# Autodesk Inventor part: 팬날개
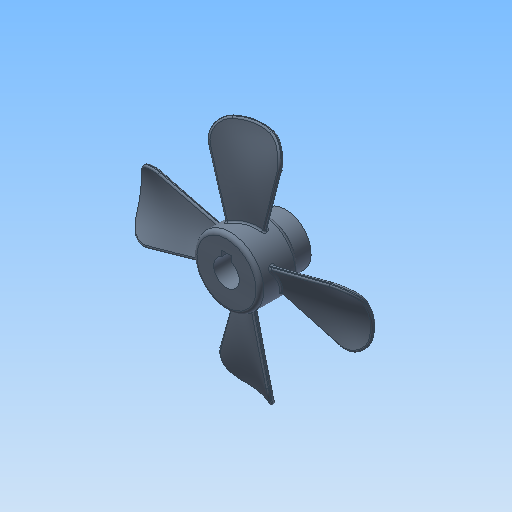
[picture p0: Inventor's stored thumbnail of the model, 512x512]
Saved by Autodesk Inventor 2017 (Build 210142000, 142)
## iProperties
Company: 한국ATC센터
Created: 2016-06
Part Number: 팬날개
Document SubType Name: Modeling
Designer: mdu
Density: 1.493 g/cm^3
Material: ABS 플라스틱
Mass: 1497.56 g
Surface Area: 466.268 cm^2
Volume: 190.529 cm^3
Appearance: 강청색
Author: mdu
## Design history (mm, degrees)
sketch "스케치1"
  geometry: L1 (-15, 0)-(15, 0); L2 (-15, 0)-(-15, 17); L3 (-15, 17)-(5, 17); L4 (5, 17)-(5, 13); L5 (5, 13)-(15, 13); L6 (15, 13)-(15, 0); 2 further points
  constraints: 12 end point, 3 parallel, 2 perpendicular, 1 coincident, 1 horizontal, 1 midpoint
  dimensions: "d0" = 30 distance of L1.start L1.end; "d8" = 34 diameter of L3 L1; "d10" = 26 diameter of L5 L1; "d32" = 20 distance of L2.end L3.end
revolve "회전1" sketch "스케치1" stored, may be unused: angle "d11" = 90 deg
node "작업 평면2"
sketch "스케치7"
  geometry: L1 (-15, 17)-(5, 17) reference; L2 (-15, -17)-(5, -17) reference; L3 (-5, 17)-(-5, -17); A1 r 35 centre (-36.399, -13.457) between (-2, -7) and (-8, 7); 1 further point
  constraints: 2 end point, 2 midpoint, 2 point on circle, 1 centre point
  dimensions: "d36" = 35 radius of A1; "d37" = 10 distance from line of A1.start L2; "d38" = 10 distance from line of A1.end L1; "d45" = 3 distance from line of A1.end L3; "d46" = 3 distance from line of A1.start L3
sketch "3D 스케치1"
  geometry: L1 through (0, 0) direction (1, 0) reference; L2 through (0, 0) direction (1, 0) reference; 13 other entities
  constraints: 2 collinear
  node "투영 원본 위치 스케치7"
sketch "스케치8"
  geometry: L1 (-15, 17)-(5, 17) reference; L2 (-15, -17)-(5, -17) reference; L3 (-5, 17)-(-5, -17); A1 r 30 centre (-28.74, -3.591) between (-3, -19) and (-9, 19); 1 further point
  constraints: 2 end point, 2 midpoint, 2 point on circle, 1 centre point
  dimensions: "d43" = 30 radius of A1; "d47" = 4 distance from line of A1.end L3; "d48" = 2 distance from line of A1.start L3; "d58" = 2 distance from line of A1.end L1; "d59" = 2 distance from line of A1.start L2
sketch "3D 스케치2"
sketch "3D 스케치3"
feature "경계 패치1" sketch "3D 스케치2", "3D 스케치3" dims "d50" = 0
feature "연장1" dims "d55" = 2
feature "두껍게 하기1" dims "d51" = 2, "d52" = 2
sketch "스케치9"
  geometry: C1 r 59 at (0, 0); 1 further point
  constraints: 1 centre point, 1 coincident
  dimensions: "d60" = 118 diameter of C1
extrude "돌출2" sketch "스케치9" distance "d62" = 200; taper "d63" = 0 deg
fillet "모깎기6" dims "d64" = 10
fillet "모깎기7" dims "d66" = 0.8
fillet "모깎기8" dims "d67" = 0.8
sketch "스케치2"
  geometry: L1 (-2.5, 6)-(-2.5, 8.8); L2 (-2.5, 8.8)-(2.5, 8.8); L3 (2.5, 8.8)-(2.5, 6); A1 r 6.5 centre (0, 0) between (-2.5, 6) and (2.5, 6); 1 further point
  constraints: 6 end point, 2 parallel, 2 point on circle, 1 centre point, 1 coincident, 1 horizontal, 1 vertical
  dimensions: "d12" = 13 diameter of A1; "d13" = 5 distance of L1.end L2.end; "d14" = 15.3 dimension on A1 L2 (computed from d12)
extrude "돌출1" cut sketch "스케치2" stored distance "d15" = 10; taper "d16" = 0 deg
chamfer "모따기1" distance "d17" = 1; stored, may be unused: second distance "d18" = 2, angle "d19" = 45 deg
node "작업 평면1"
sketch "스케치3"
  geometry: L1 (5, -13)-(5, 13) reference; 3 further points
  constraints: 1 horizontal alignment, 1 midpoint
  dimensions: "d20" = 5 distance from line of L1 point (0, 0)
hole "구멍1" sketch "스케치3" at (0, 0) diameter "d21" = 2.459; stored, may be unused: countersink angle "d25" = 90 deg, drill point angle "d27" = 118 deg; dims "d22" = 6, "d23" = 4, "d24" = 2, "d26" = 8
fillet "모깎기9" dims "d77" = 2
fillet "모깎기10" dims "d78" = 2
fillet "모깎기11" dims "d79" = 2
node "솔리드1"
pattern_circular "원형 패턴1" dims angle "d69" = 360 deg
pattern_circular "원형 패턴2" dims angle "d72" = 360 deg
pattern_circular "원형 패턴3" dims angle "d75" = 360 deg
node "투영 원본 위치 스케치8"
node "곡면1"
node "곡면2"
node "곡면3"
node "곡면4"
feature "경계 패치2"
feature "경계 패치3"
feature "경계 패치4"
